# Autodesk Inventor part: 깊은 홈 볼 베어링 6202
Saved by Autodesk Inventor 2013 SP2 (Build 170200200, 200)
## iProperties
Created: 2024-11
Part Number: 깊은 홈 볼 베어링 6202
Material: Generic
Document SubType Name: Modeling
Designer: a
Density: 1 g/cm^3
Author: a
변환 표준: STEP AP214IS
전처리기: Build: 200, Release: 2013 SP2 Update 6 - Date: Thu 07/17/2014
전송 단위: 밀리미터
불확실성: 0.01
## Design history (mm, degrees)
node "깊음 홈 볼 베어링 62021"
body "Solid1"
node "Solid1_1"
node "Solid1_2"
node "Solid1_3"
node "Solid1_4"
node "Solid1_5"
node "Solid1_6"
node "Solid1_7"
node "Solid1_8"
node "Solid1_9"
node "기준1"
node "기준2"
node "기준3"
node "기준4"
node "기준5"
node "기준6"
node "기준7"
node "기준8"
node "기준9"
node "기준10"
